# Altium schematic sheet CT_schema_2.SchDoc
size 307 x 173 mm
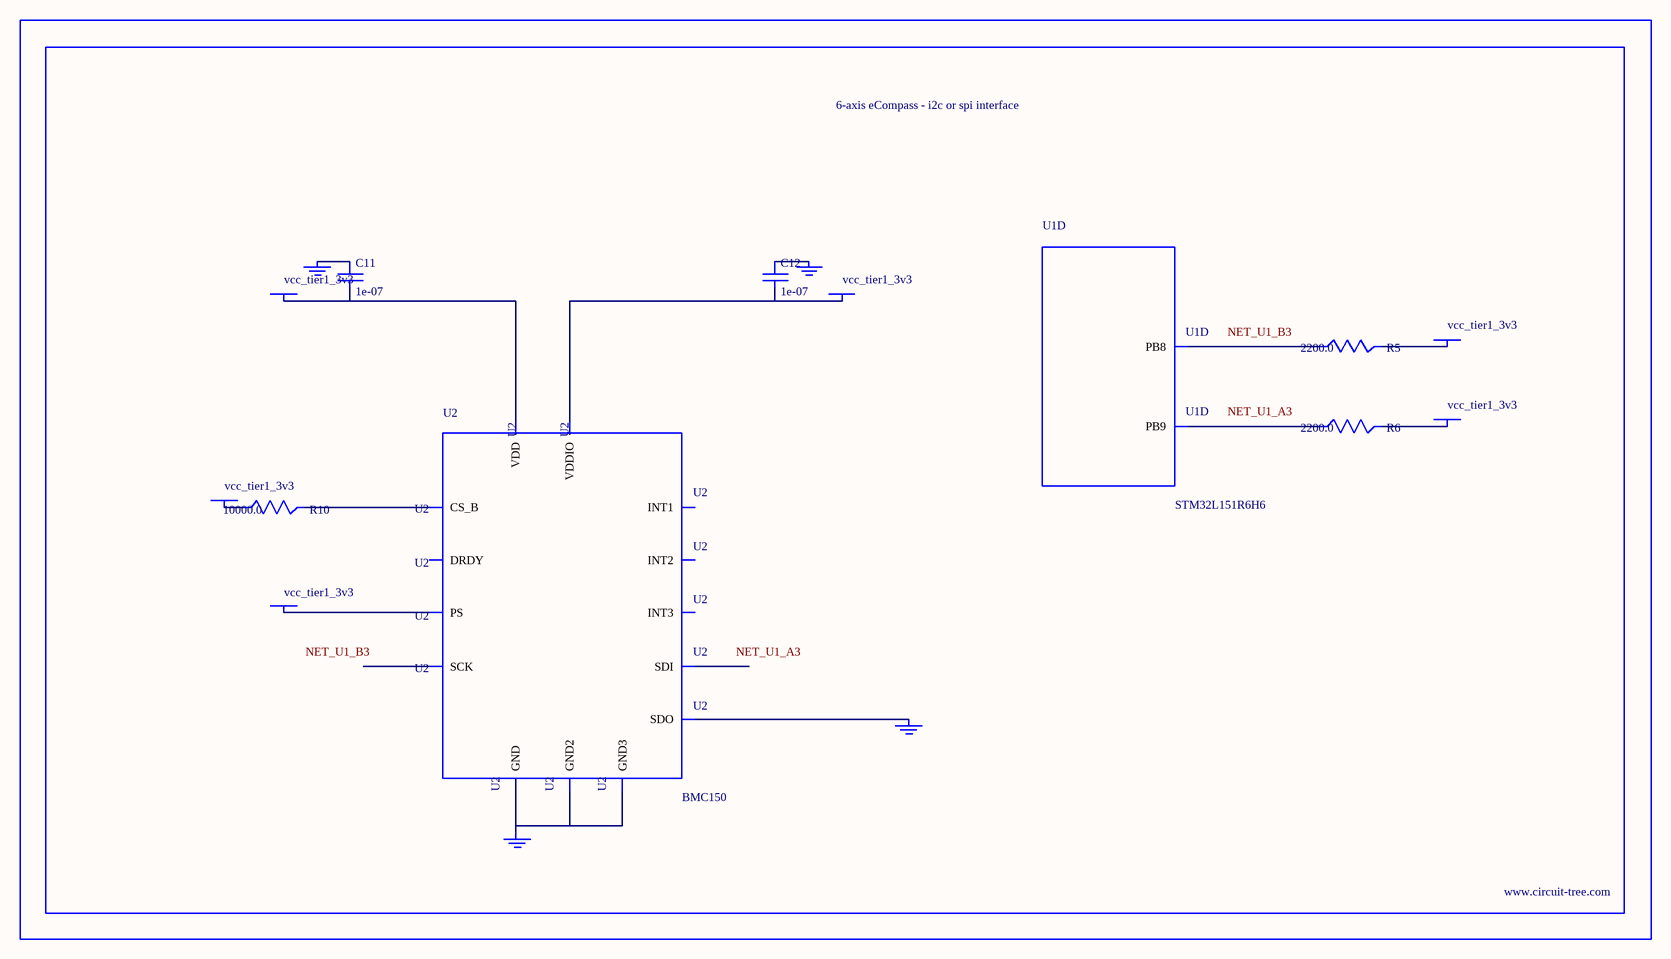
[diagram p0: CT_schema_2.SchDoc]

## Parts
BORDER1  (no value)
C11  1e-07  [C0402]
C12  1e-07  [C0402]
GND_INSTANCE_1_0  (no value)
GND_INSTANCE_1_1  (no value)
GND_INSTANCE_1_2  (no value)
GND_INSTANCE_1_3  (no value)
POWER_INSTANCE_1_0  vcc_tier1_3v3
POWER_INSTANCE_1_1  vcc_tier1_3v3
POWER_INSTANCE_1_2  vcc_tier1_3v3
POWER_INSTANCE_1_3  vcc_tier1_3v3
POWER_INSTANCE_1_4  vcc_tier1_3v3
POWER_INSTANCE_1_5  vcc_tier1_3v3
R5  2200.0  [R0603]
R6  2200.0  [R0603]
R10  10000.0  [R0603]
U1  STM32L151R6H6  [TFBGA64]  (part D of 6)
U2  BMC150  [LGA14R35P5X6_200X200X100]

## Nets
NetC11_1: C11.1 GND_INSTANCE_1_1.0(GND)
NetC11_2: C11.2 POWER_INSTANCE_1_0.0(PWR) U2.8(VDD)
NetC12_1: C12.1 GND_INSTANCE_1_2.0(GND)
NetC12_2: C12.2 POWER_INSTANCE_1_1.0(PWR) U2.10(VDDIO)
NetGND_INSTANCE_1_0_0: GND_INSTANCE_1_0.0(GND) U2.1(SDO)
NetGND_INSTANCE_1_3_0: GND_INSTANCE_1_3.0(GND) U2.6(GND) U2.7(GND2) U2.9(GND3)
NetPOWER_INSTANCE_1_2_0: POWER_INSTANCE_1_2.0(PWR) R10.1
NetPOWER_INSTANCE_1_3_0: POWER_INSTANCE_1_3.0(PWR) U2.13(PS)
NetPOWER_INSTANCE_1_4_0: POWER_INSTANCE_1_4.0(PWR) R5.2
NetPOWER_INSTANCE_1_5_0: POWER_INSTANCE_1_5.0(PWR) R6.2
NetR5_1: R5.1 U1.B3(PB8)
NetR6_1: R6.1 U1.A3(PB9)
NetR10_2: R10.2 U2.12(CS_B)

Not connected (* = marked no-connect by the designer): U2 2(INT1) 3(INT2) 4(DRDY) 5(INT3) 11(SCK) 14(SDI)

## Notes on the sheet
- Labels drawn without touching a wire or pin: NET_U1_A3, NET_U1_B3

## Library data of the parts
BORDER1 = BORDER_PAGE1
C11 C12 = C0402C104K3RACTU
GND_INSTANCE_1_0-GND_INSTANCE_1_3 = GND
POWER_INSTANCE_1_0-POWER_INSTANCE_1_5 = PWR
R5 R6 = RC0603JR-072K2L
R10 = RC0603JR-0710KL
